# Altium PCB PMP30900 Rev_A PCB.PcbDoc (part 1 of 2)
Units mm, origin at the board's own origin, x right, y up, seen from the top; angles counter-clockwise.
Board outline 88.9 x 46.99 mm, 6 copper layers (Top Layer, Layer 2, Layer 3, Layer 4, Layer 5, Bottom Layer), stack 1.76 mm thick; 101 components, 54 nets, 324 pads, 212 vias.
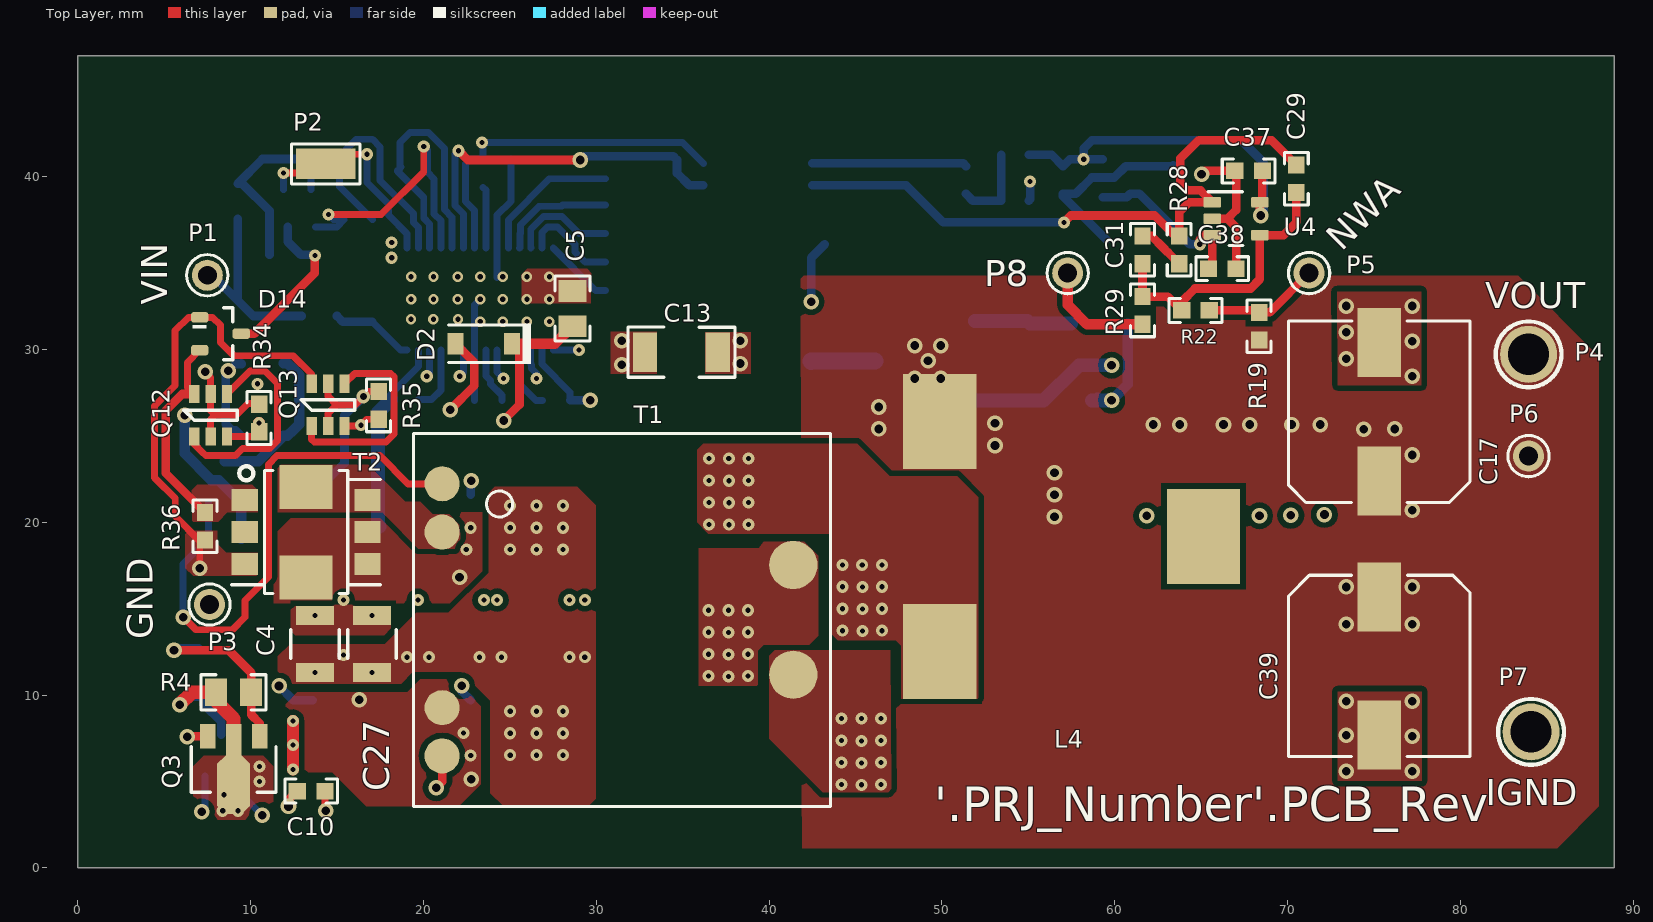
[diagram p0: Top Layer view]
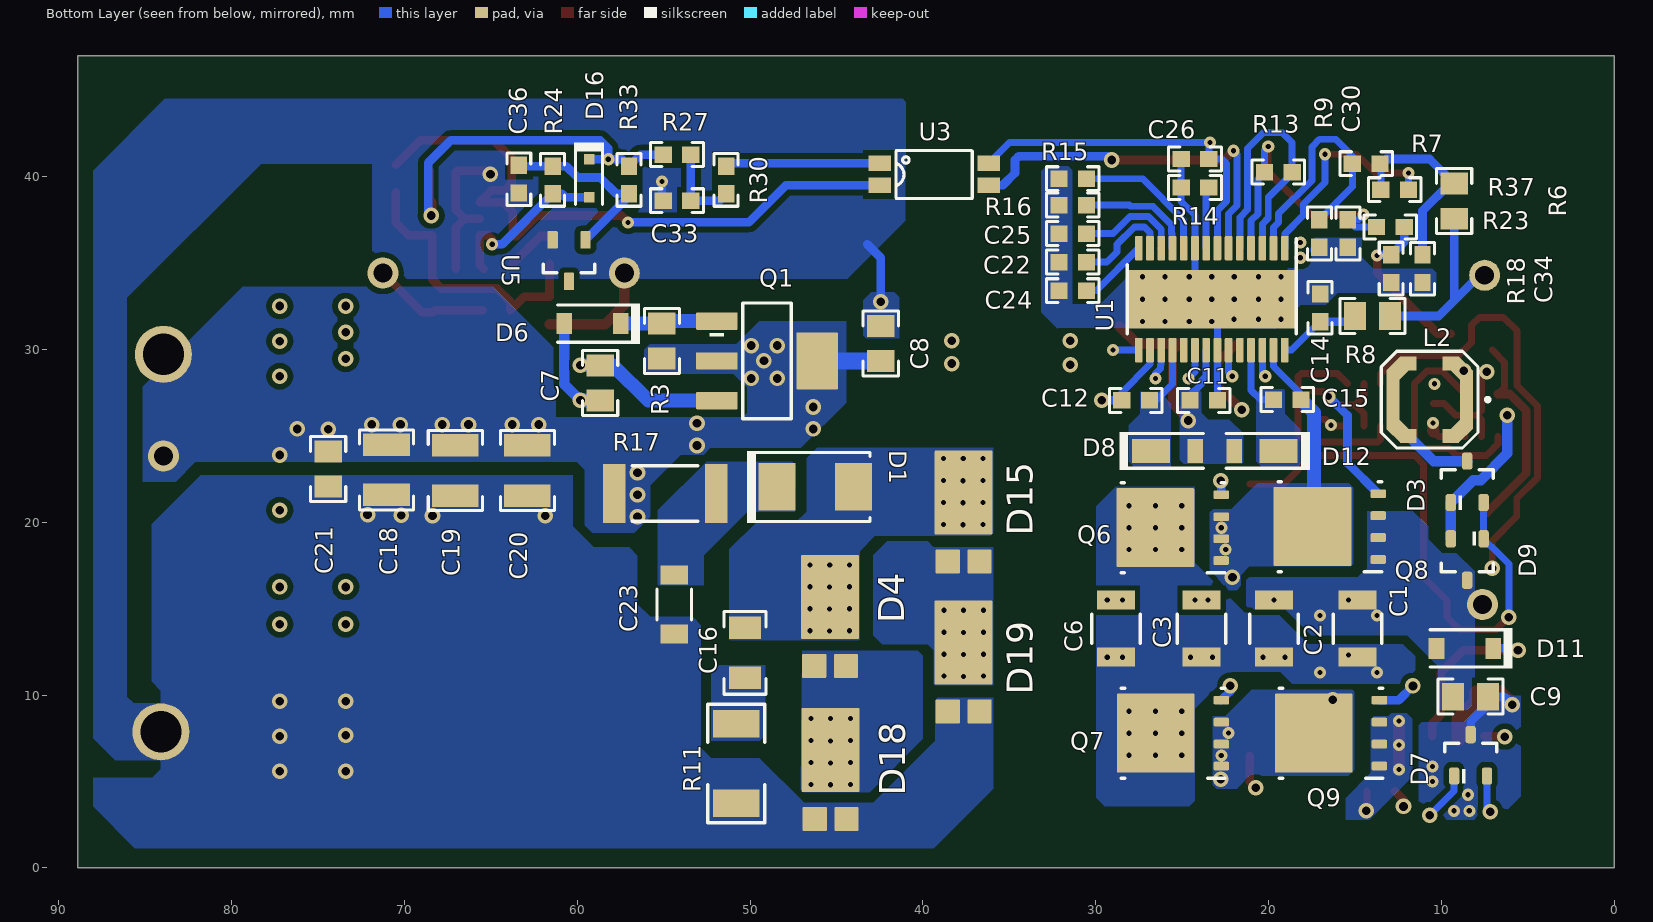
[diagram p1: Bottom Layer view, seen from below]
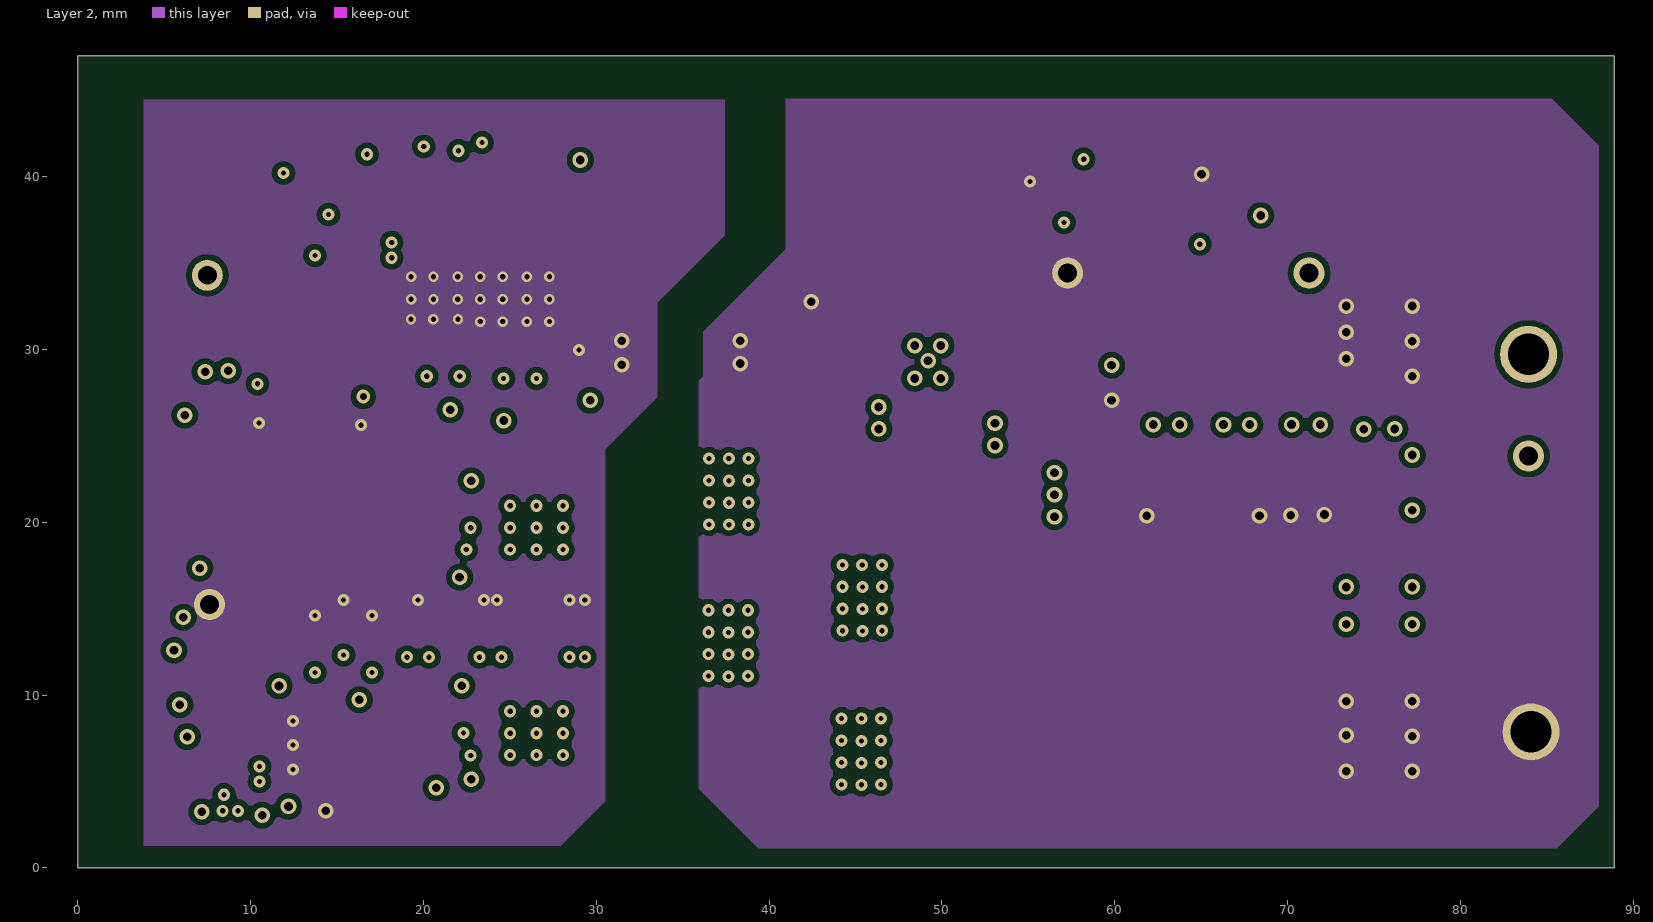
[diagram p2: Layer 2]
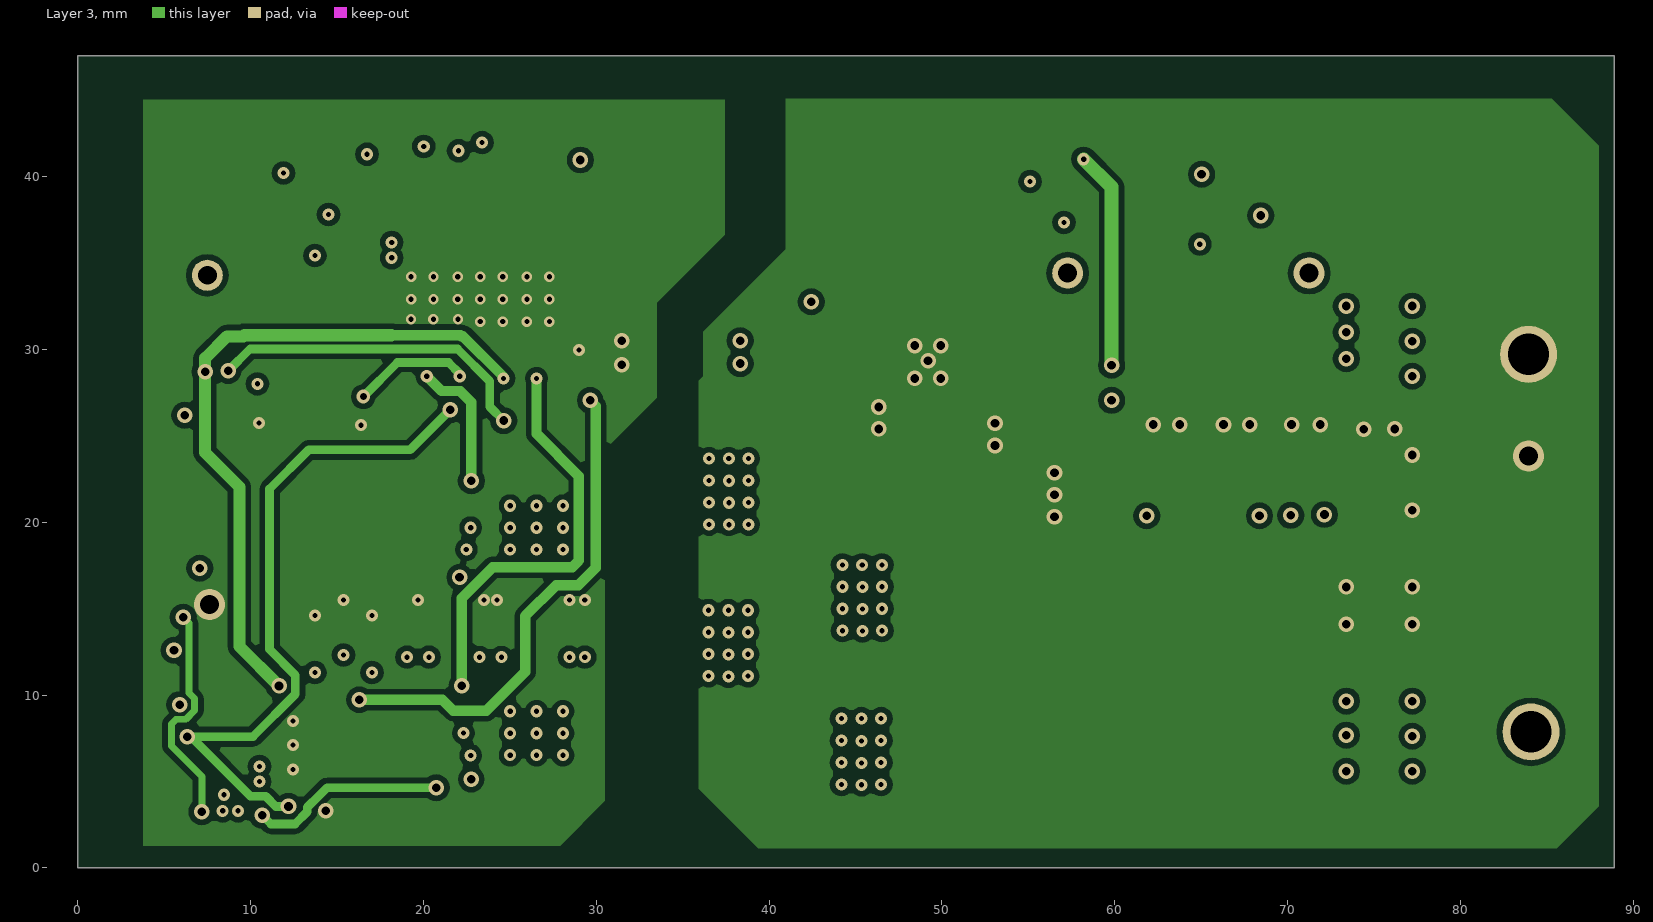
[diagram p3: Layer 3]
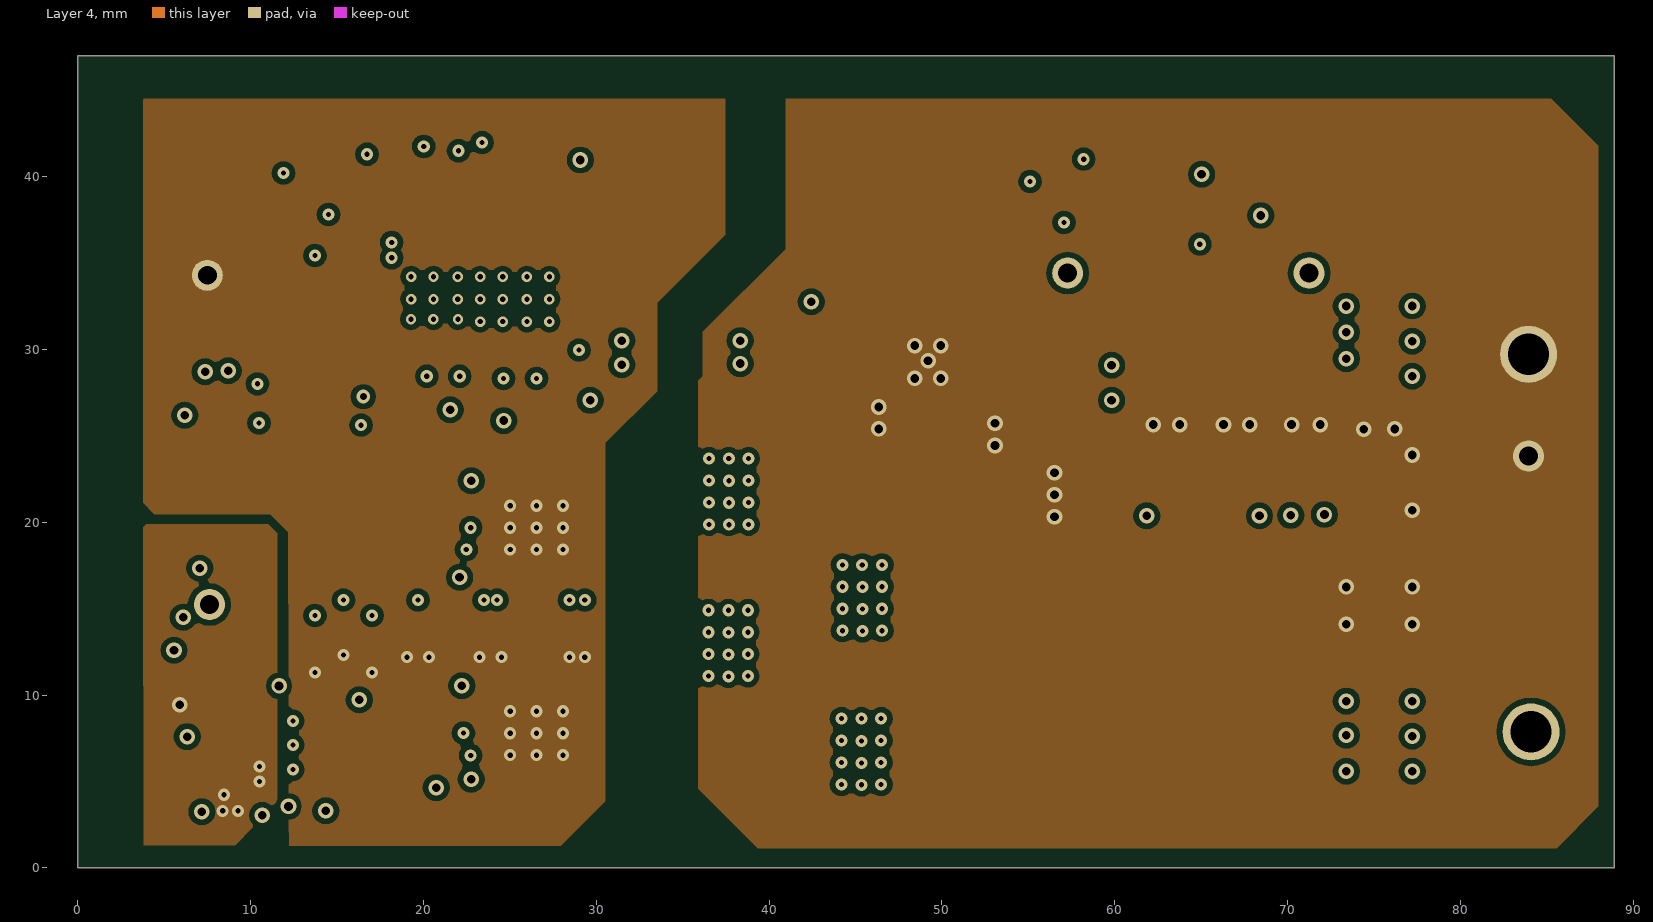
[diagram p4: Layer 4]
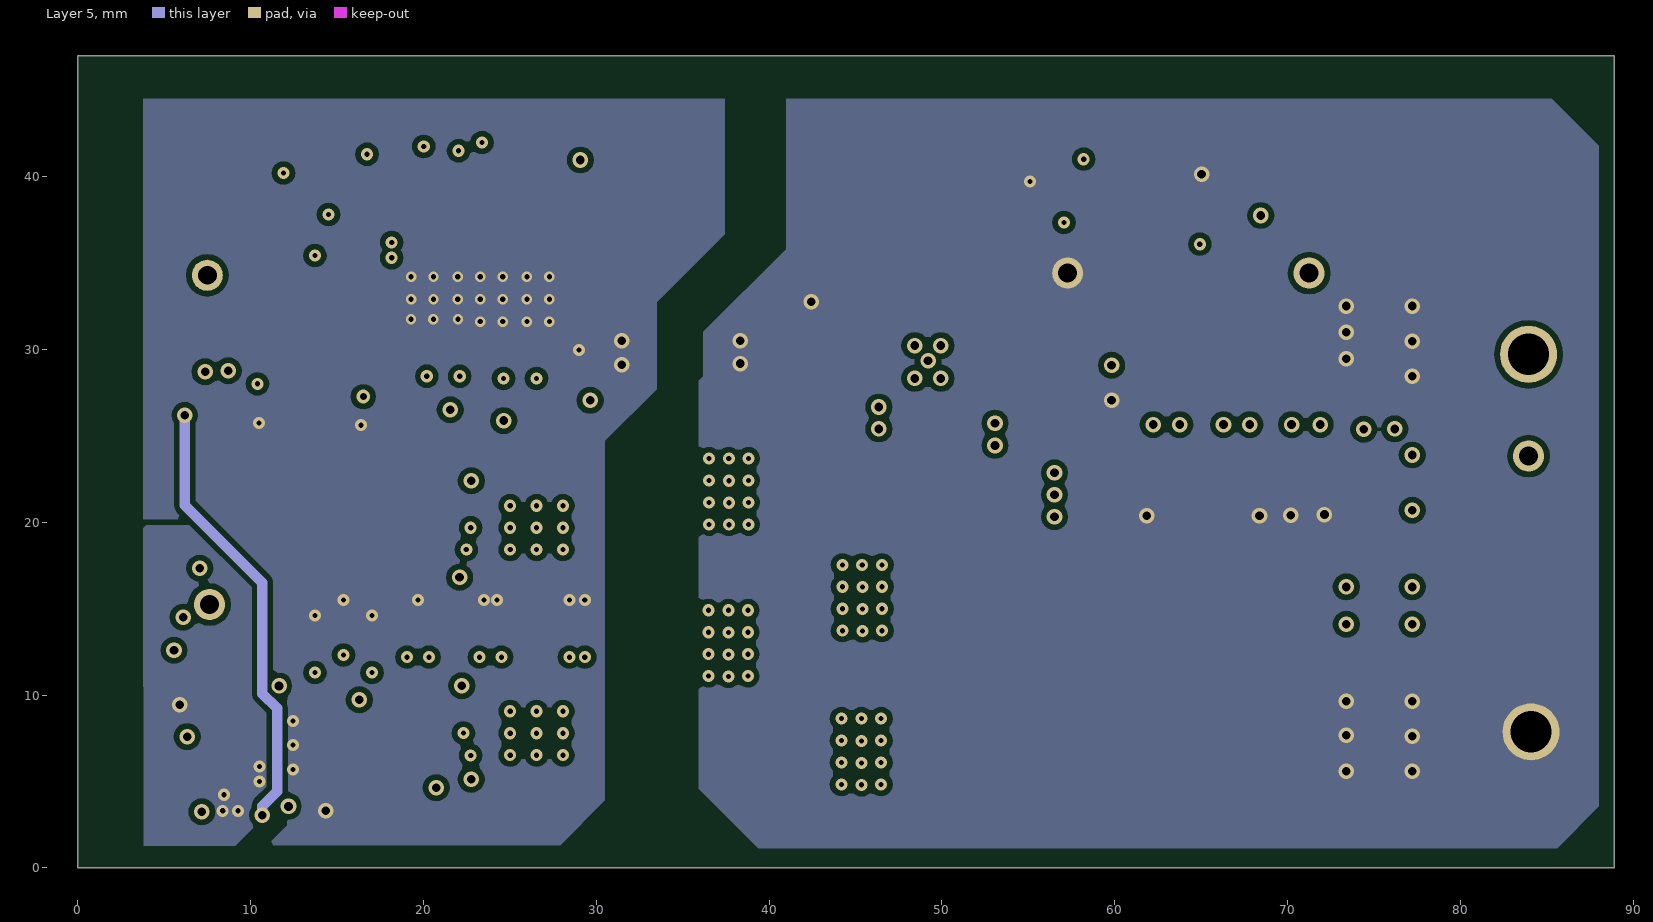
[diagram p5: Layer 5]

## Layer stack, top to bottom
Top Solder: solder mask 0.0102, Solder Resist, Dk 3.5
Top Layer: signal copper 0.07
Dielectric 1: prepreg 0.232, PP-006, Dk 4.1
Layer 2: signal copper 0.035
Dielectric 2: prepreg 0.36, PP-006, Dk 4.1
Layer 3: signal copper 0.035
Dielectric 3: prepreg 0.296, FR-4, Dk 4.8
Layer 4: signal copper 0.035
Dielectric 4: prepreg 0.36, PP-006, Dk 4.1
Layer 5: signal copper 0.035
Dielectric 5: prepreg 0.232, PP-006, Dk 4.1
Bottom Layer: signal copper 0.07
Bottom Solder: solder mask 0.0102, Solder Resist, Dk 3.5

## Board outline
0,0 88.9,0 88.9,46.99 0,46.99

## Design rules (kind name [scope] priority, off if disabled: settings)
AcuteAngle [All] p1: minimum=4.50000000000000E+0001 checktracksonly=FALSE
AssemblyTestPointUsage [All] p1: valid=2
BoardOutlineClearance BoardOutlineClearance_MountingHoles [OnCopper and InComponentClass('Mounting Holes')] p1: gap=1 ignorepadtopadclearanceinfootprint=FALSE
BoardOutlineClearance BoardOutlineClearance_Poly [OnCopper and IsPoly] p2: gap=0.4 ignorepadtopadclearanceinfootprint=FALSE
BoardOutlineClearance [OnCopper and Not InComponentClass('Logo') and not InComponentClass('FiducialMark') and not InRegion(1000,500,4000,800) and not InPoly] p3: gap=1.905 ignorepadtopadclearanceinfootprint=FALSE
Clearance Clearance_Keepouts [((IsTrack Or IsArc) And Not InPoly) And IsFree and IsKeepOut vs ((IsTrack Or IsArc) And Not InPoly) And IsFree and IsKeepOut] p1: gap=0 ignorepadtopadclearanceinfootprint=FALSE
Clearance Clearance_Poly [InPolygon] p2: gap=0.32 ignorepadtopadclearanceinfootprint=TRUE
Clearance Clearance_FiducialMark [IsKeepOut and InComponentClass('FiducialMark') vs IsPad and InComponentClass('FiducialMark')] p3: gap=0 ignorepadtopadclearanceinfootprint=FALSE
Clearance [All] p4: gap=0.2 ignorepadtopadclearanceinfootprint=TRUE
ComponentClearance ComponentClearance_MountingHoles_FiducialMarks [InComponentClass('Mounting Holes') vs InComponentClass('FiducialMark')] p1: gap=1.27 collisioncheckmode=3 verticalgap=0.254 showdistances=FALSE
ComponentClearance ComponentClearance_Shunt [InComponentClass('Header') vs InComponentClass('Shunt')] p2: gap=0 collisioncheckmode=3 verticalgap=0 showdistances=FALSE
ComponentClearance ComponentClearance_Logo [InComponentClass('Logo')] p3: gap=1.27 collisioncheckmode=3 verticalgap=0.254 showdistances=FALSE
ComponentClearance ComponentClearance_ScrewToNut [(HasFootprint('NY PMS 440 0025 PH')) vs (HasFootprint('Keystone_1902C'))] p4: gap=0.127 collisioncheckmode=3 verticalgap=0.254 showdistances=FALSE
ComponentClearance ComponentClearance_MountingHoles [InComponentClass('Mounting Holes')] p5: gap=6.35 collisioncheckmode=3 verticalgap=2540 showdistances=FALSE
ComponentClearance ComponentClearance_SmallPassives [HasFootprint('0201*') or HasFootprint('0402*') or HasFootprint('0508') or HasFootprint('0603*') or HasFootprint('0612') or HasFootprint('0805*') or HasFootprint('0815*') or HasFootprint('0830*') or HasFootprint('1206*') or HasFootprint('1210*') or HasFootprint('1808*') or HasFootprint('1812*') or HasFootprint('1825*') or HasFootprint('2010*') or HasFootprint('2220*') or HasFootprint('2225*') or HasFootprint('2512*') or HasFootprint('2728*') or HasFootprint('3518*') vs HasFootprint('0201*') or HasFootprint('0402*') or HasFootprint('0508') or HasFootprint('0603*') or HasFootprint('0612') or HasFootprint('0805*') or HasFootprint('0815*') or HasFootprint('0830*') or HasFootprint('1206*') or HasFootprint('1210*') or HasFootprint('1808*') or HasFootprint('1812*') or HasFootprint('1825*') or HasFootprint('2010*') or HasFootprint('2220*') or HasFootprint('2225*') or HasFootprint('2512*') or HasFootprint('2728*') or HasFootprint('3518*')] p6: gap=0.38 collisioncheckmode=3 verticalgap=0.254 showdistances=FALSE
ComponentClearance ComponentClearance_THtoSMT [IsThruComponent vs IsSMTComponent] p7: gap=1.016 collisioncheckmode=3 verticalgap=0.762 showdistances=FALSE
ComponentClearance ComponentClearance_THtoTH [IsThruComponent vs IsThruComponent] p8: gap=0.762 collisioncheckmode=3 verticalgap=0.762 showdistances=FALSE
ComponentClearance [All] p9: gap=0.762 collisioncheckmode=3 verticalgap=0.254 showdistances=FALSE
DiffPairsRouting [All] p1: maxlimit=2.54 minlimit=0.254 mostfreqgap=0.254 toplayer_minwidth=0.381 toplayer_maxwidth=0.381 toplayer_prefwidth=0.381 midlayer1_minwidth=0.381 midlayer1_maxwidth=0.381 midlayer1_prefwidth=0.381 midlayer2_minwidth=0.381 midlayer2_maxwidth=0.381 midlayer2_prefwidth=0.381 midlayer3_minwidth=0.381 midlayer3_maxwidth=0.381 midlayer3_prefwidth=0.381 midlayer4_minwidth=0.381 midlayer4_maxwidth=0.381 midlayer4_prefwidth=0.381 bottomlayer_minwidth=0.381 bottomlayer_maxwidth=0.381 bottomlayer_prefwidth=0.381 maxuncoupledlength=25.4
FabricationTestPointUsage TestPointUsage [All] p1: valid=2 allowmultiple=FALSE
FabricationTestpoint Testpoint [All] p1: side=3 testpointundercomponent=TRUE minsize=1.016 maxsize=2.54 preferedsize=1.524 minholesize=0 maxholesize=1.016 preferedholesize=0.813 testpointgrid=0.025 allowsidetop=TRUE allowsidebottom=TRUE usegrid=TRUE gridtolerance=0
FanoutControl Fanout_LCC [IsLCC] p1: bgadir=Out bgaviamode=Centered fanoutstyle=Auto fanoutdirection=Alternating viagrid=0.025 // Fanout_LCC (Default Rule)
FanoutControl Fanout_BGA [IsBGA] p2: bgadir=Out bgaviamode=Centered fanoutstyle=Auto fanoutdirection=Alternating viagrid=0.025 // Fanout_BGA (Default Rule)
FanoutControl Fanout_Default [All] p4: bgadir=Out bgaviamode=Centered fanoutstyle=Auto fanoutdirection=Alternating viagrid=0.025 // Fanout_Default (Default Rule)
FanoutControl Fanout_Small [(CompPinCount < 5)] p5: bgadir=Out bgaviamode=Centered fanoutstyle=Auto fanoutdirection=OutThenIn viagrid=0.025 // Fanout_Small (Default Rule)
HoleSize [All] p1: absolutevalues=TRUE maxlimit=6.375 minlimit=0.3 maxpercent=80.000 minpercent=20.000
MinimumAnnularRing MinimumAnnularRing_ThermalPadVias [IsVia and InAnyComponent] p1: minimumring=0.15
MinimumAnnularRing [All] p2: minimumring=0.2
MinimumSolderMaskSliver MinimumSolderMaskSliver_Logo [InComponentClass('Logo') vs InComponentClass('Logo')] p1: minsoldermaskwidth=0.018
MinimumSolderMaskSliver [All] p2: minsoldermaskwidth=0.1
PlaneConnect [All] p1: planeconnectstyle=Relief reliefexpansion=0.254 reliefentries=4 reliefconductorwidth=0.254 reliefairgap=0.254
PolygonConnect PolygonConnect_1 [All vs InComponent('P5')] p1: connectstyle=NoConnect reliefconductorwidth=0.254 reliefentries=4 polygonreliefangle="90 Angle" airgapwidth=0.254
PolygonConnect [All] p2: connectstyle=Direct reliefconductorwidth=0.254 reliefentries=4 polygonreliefangle="90 Angle" airgapwidth=0.254
RoutingVias ThermalPadVias [IsVia and InAnyComponent] p1: holewidth=0.2 width=0.5 viastyle="Through Hole" minholewidth=0.2 minwidth=0.5 maxholewidth=0.33 maxwidth=0.6
RoutingVias [All] p2: holewidth=0.5 width=0.9 viastyle="Through Hole" minholewidth=0.3 minwidth=0.6 maxholewidth=1.016 maxwidth=1.651
SilkToBoardRegionClearance [Not ((IsComment or IsDesignator) And (Hide <> 'False')) and not InRegion(1000,500,4000,800)] p1:
SilkToSilkClearance SilkToSilkClearance_Pb-FreeLogo [(HasFootprint('Pb-Free_Overlay_Medium') OR HasFootprint('Pb-Free_Overlay_Small')) vs (HasFootprint('Pb-Free_Overlay_Medium') OR HasFootprint('Pb-Free_Overlay_Small'))] p1: silktosilkclearance=0
SilkToSilkClearance [All] p2: silktosilkclearance=0.1
SilkToSolderMaskClearance SilkToComponentPadClearance [(IsPad or IsFill or IsRegion) and InAnycomponent] p1: minsilkscreentomaskgap=0.127 clearancetoexposedcopper=TRUE
SilkToSolderMaskClearance "Silk to Solder Mask Opening" [All] p2: minsilkscreentomaskgap=0.1 clearancetoexposedcopper=FALSE
SolderMaskExpansion [All] p1: expansion=0.05 istentingtop=FALSE
UnRoutedNet [All] p1: checkbadconnections=TRUE
Width [All] p1: maxlimit=2.54 minlimit=0.152 preferedwidth=0.254 checkconnectedcopper=TRUE
14 further rules are at their usual default settings.

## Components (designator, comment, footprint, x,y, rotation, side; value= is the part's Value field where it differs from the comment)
C1 "C3225X5R1H106K250AB" 1210_280 14.859,13.843 r90 bottom value=10uF
C2 "C3225X5R1H106K250AB" 1210_280 19.685,13.843 r90 bottom value=10uF
C3 "C3225X5R1H106K250AB" 1210_280 23.876,13.843 r90 bottom value=10uF
C4 "C3225X5R1H106K250AB" 1210_280 13.716,12.954 r90 top value=10uF
C5 "GRM21BR71C225KA12L" 0805_HV 28.626,32.359 r90 top value=2.2uF
C6 "C3225X5R1H106K250AB" 1210_280 28.829,13.843 r90 bottom value=10uF
C7 "GRM21BR71E225KA73L" 0805_HV 58.674,28.067 r270 bottom value=2.2uF
C8 "GRM21AR72A224KAC5L" 0805_HV 42.439,30.337 r90 bottom value=0.22uF
C9 "GRM21BR71H105KA12L" 0805_HV 8.307,9.91 r0 bottom value=1uF
C10 "C1608X7R1C105K080AC" 0603 13.5,4.445 r0 top value=1uF
C11 "C1608X7R1C105K080AC" 0603 23.749,27.051 r180 bottom value=1uF
C12 "06033C104KAT2A" 0603 27.686,27.051 r180 bottom value=0.1uF
C13 "C1808C272KGRACTU" 1808 34.925,29.837 r0 top value=2700pF
C14 "GRM188R72A104KA35D" 0603 17.018,32.409 r90 bottom value=0.1uF
C15 "06033C104KAT2A" 0603 18.916,27.096 r0 bottom value=0.1uF
C16 "GRM31A5C2J101JW01D" 1206 50.292,12.446 r270 bottom value=100pF
C17 "EEHZC1K470P" SM_RADIAL_10BMM 75.311,26.393 r90 top value=47uF
C18 "GRM32ER72A225KA35L" 1210_270 71.037,23.03 r270 bottom value=2.2uF
C19 "GRM32ER72A225KA35L" 1210_270 67.056,22.995 r270 bottom value=2.2uF
C20 "GRM32ER72A225KA35L" 1210_270 62.885,22.995 r270 bottom value=2.2uF
C21 "C0805C104K1RACTU" 0805_HV 74.413,23.084 r270 bottom value=0.1uF
C22 "GRM188R71C223KA01D" 0603 31.331,35.052 r0 bottom value=0.022uF
C23 "GRM31CR72E104KW03L" 1206_180 54.379,15.239 r270 bottom value=0.1uF
C24 "GRM188R71C563KA01D" 0603 31.331,33.401 r0 bottom value=0.056uF
C25 "GRM188R71C103KA01D" 0603 31.331,36.703 r0 bottom value=0.01uF
C26 "06033C104KAT2A" 0603 24.257,41.021 r0 bottom value=0.1uF
C27 "C3225X5R1H106K250AB" 1210_280 17.018,12.954 r90 top value=10uF
C29 "GRM1885C1H470JA01D" 0603 70.506,39.878 r90 top value=47pF
C30 "C1608C0G1H101J080AE" 0603 15.409,36.707 r270 bottom value=100pF
C31 "GRM188R71C103KA01D" 0603 63.73,35.765 r90 top value=0.01uF
C33 "GRM188R71C103KA01D" 0603 54.229,38.608 r0 bottom value=0.01uF
C34 "GRM1885C1E102JA01D" 0603 11.091,34.675 r270 bottom value=1000pF
C36 "GRM1885C1E102JA01D" 0603 63.385,39.855 r270 bottom value=1000pF
C37 "06033C104KAT2A" 0603 67.746,40.33 r0 top value=0.1uF
C38 "GRM188R70J474KA01D" 0603 66.222,34.671 r0 top value=0.47uF
C39 "EEHZC1K470P" SM_RADIAL_10BMM 75.311,11.684 r270 top value=47uF
D1 "MBRS3200T3G" SMB 46.228,22.048 r180 bottom value=200V
D2 "B130LAW-7-F" SOD-123 23.487,30.327 r180 top value=30V
D3 "CMPSH-3CE" SOT-23 8.506,22.34 r90 bottom value=40V
D4 "MBR10200UPS" TO-277 45.37,13.679 r0 bottom
D6 "MMSZ5243B-7-F" SOD-123 59.118,31.496 r0 bottom value=13V
D7 "CMPSH-3CE" SOT-23 8.307,6.512 r90 bottom value=40V
D8 "DFLS1100-7" PowerDI123 25.527,24.13 r180 bottom value=100V
D9 "CMPSH-3AE" SOT-23 8.506,17.843 r270 bottom value=40V
D11 "MMSZ5241B-7-F" SOD-123 8.636,12.7 r0 bottom value=11V
D12 "DFLS1100-7" PowerDI123 20.701,24.13 r0 bottom value=100V
D14 "CMPSH-3CE" SOT-23 8.254,30.909 r0 top value=40V
D15 "MBR10200UPS" TO-277 37.643,19.722 r0 bottom
D16 "BAT54WS-7-F" SOD-323 59.315,39.907 r270 bottom value=30V
D18 "MBR10200UPS" TO-277 45.339,4.826 r0 bottom
D19 "MBR10200UPS" TO-277 37.643,11.049 r0 bottom
L2 "LPS5030-225MLB" LPS5030 10.68,27.096 r0 bottom value=2.2mH
L4 "SER2013-472MLB" LIBRARYSOURCE=Vault 57.511,19.182 r0 top
P1 "3104-2-00-34-00-00-08-0" 3104-2 7.493,34.29 r0 top
P2 "5015" Testpoint_Keystone_Miniature 14.351,40.746 r0 top
P3 "3104-2-00-34-00-00-08-0" 3104-2 7.62,15.24 r0 top
P4 "3231-2-00-34-00-00-08-0" 3231-2 83.947,29.718 r0 top
P5 "3104-2-00-34-00-00-08-0" 3104-2 71.247,34.417 r0 top
P6 "3104-2-00-34-00-00-08-0" 3104-2 83.947,23.827 r0 top
P7 "3231-2-00-34-00-00-08-0" 3231-2 84.09,7.874 r0 top
P8 "3104-2-00-34-00-00-08-0" 3104-2 57.277,34.417 r0 top
Q1 "FZT493TA" SOT-223 49.022,29.337 r180 bottom
Q3 "FCX690BTA" SOT-89-3 9.017,5.715 r270 top value="45 V"
Q6 "CSD18504Q5A" DQJ0008A 25.538,19.685 r0 bottom value=40V
Q7 "CSD18504Q5A" DQJ0008A 25.526,7.8 r0 bottom value=40V
Q8 "CSD18504Q5A" DQJ0008A 16.452,19.748 r0 bottom value=40V
Q9 "CSD18504Q5A" DQJ0008A 16.382,7.8 r0 bottom value=40V
Q12 "DMN5L06DMK-7" SOT-26 7.681,26.194 r90 top value=50V
Q13 "DMN5L06DMK-7" SOT-26 14.482,26.793 r90 top value=50V
R3 "ERJ-6GEYJ104V" 0805_HV 55.104,30.48 r270 bottom value=100k
R4 "ERJ-6GEYJ512V" 0805_HV 9.017,10.16 r180 top value=5.1k
R6 "CRCW0805100KFKEA" 0805_HV 9.256,38.579 r270 bottom value=100k
R7 "CRCW06032K61FKEA" 0603 14.351,40.746 r180 bottom value=2.61k
R8 "ERJ-6GEYJ200V" 0805_HV 13.979,31.934 r180 bottom value=20
R9 "CRCW06031K58FKEA" 0603 17.06,36.707 r90 bottom value=1.58k
R11 "CRCW2010100RJNEF" 2010 50.797,6.044 r90 bottom value=100
R13 "CRCW06031K69FKEA" 0603 19.431,40.259 r180 bottom value=1.69k
R14 "CRCW060324K0JNEA" 0603 24.257,39.37 r180 bottom value=24k
R15 "CRCW060330K1FKEA" 0603 31.331,39.878 r180 bottom value=30.1k
R16 "CRCW060320K0FKEA" 0603 31.331,38.354 r180 bottom value=20.0k
R17 "CRCW251210K0JNEG" 2512 54.921,21.66 r0 bottom value=10k
R18 "CRCW060315R0FKEA" 0603 12.902,34.678 r90 bottom value=15.0
R19 "ERJ-3EKF49R9V" 0603 68.351,31.344 r270 top value=49.9
R22 "RC0603FR-07680KL" 0603 64.672,32.258 r0 top value=680k
R23 "CRCW0603499RFKEA" 0603 12.954,37.084 r180 bottom value=499
R24 "CRCW06035K11FKEA" 0603 61.427,39.807 r90 bottom value=5.11k
R27 "CRCW060347R0JNEAHP" 0603 54.229,41.275 r0 bottom value=47
R28 "CRCW060310K0FKEA" 0603 61.606,35.765 r270 top value=10.0k
R29 "CRCW060315K0FKEA" 0603 61.606,32.258 r270 top value=15.0k
R30 "CRCW06031K82FKEA" 0603 51.39,39.807 r270 bottom value=1.82k
R33 "RC0603FR-07100KL" 0603 57.006,39.807 r90 bottom value=100k
R34 "CRCW060310K0FKEA" 0603 10.49,26.035 r90 top value=10.0k
R35 "CRCW060310K0FKEA" 0603 17.409,26.761 r90 top value=10.0k
R36 "CRCW060310K0FKEA" 0603 7.357,19.768 r90 top value=10.0k
R37 "CRCW06030000Z0EA" 0603 12.7,39.243 r0 bottom value=0
T1 "ZB1292-AL" PA0876 31.496,14.351 r0 top
T2 "PA1005.100NL" P82xx 13.208,19.431 r0 top
U1 "LM5045MHX/NOPB" PWP0028A_N 23.284,32.909 r270 bottom
U3 "TCMT1107" SOP-4 39.345,40.132 r180 bottom
U4 "LM8261M5X/NOPB" DBV0005A_N 67.023,37.565 r0 top
U5 "LM4041B12IDBZT" DBZ0003A_N 60.477,35.141 r270 bottom

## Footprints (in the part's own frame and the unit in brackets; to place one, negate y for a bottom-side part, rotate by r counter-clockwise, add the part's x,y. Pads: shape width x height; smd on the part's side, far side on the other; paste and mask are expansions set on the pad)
0603 [mm] "0603 from SM-752 data"
  rect 1x0.95 smd: 1(-0.8,0) 2(0.8,0)
  silkscreen extent -1.52,-0.69 1.52,0.69, body extent -0.87,-0.47 0.87,0.47, height 1
0805_HV [mil] "0805 with 30mil clearance between pads"
  rect 50x63 smd: 1(-40,0) 2(40,0)
  silkscreen extent -74,-40 74,40, body extent -43,-29 43,29, height 57
1206 [mm] "1206 from SM-752 data"
  rect 1.3x1.85 smd: 1(-1.45,0) 2(1.45,0)
  silkscreen extent -2.4,-1.21 2.4,1.21, body extent -1.7,-0.9 1.7,0.9, height 1.35
1206_180 [mm] "1206_180"
  rect 1.1x1.6 smd: 1(-1.7,0) 2(1.7,0)
  silkscreen extent -0.9,-1 0.9,1, body extent -1.75,-0.95 1.75,0.95, height 1.8
1210_270 [mm] "1210"
  rect 1.3x2.7 smd: 1(-1.45,0) 2(1.45,0)
  silkscreen extent -2.32,-1.57 2.32,1.57, body extent -1.7,-1.35 1.7,1.35, height 2.7
1210_280 [mm] "SMD, 2-Leads, Body 3.6x2.8mm, Height 2.8mm"
  rect 1.1x2.2 smd: 1(-1.65,0) 2(1.65,0)
  silkscreen extent -0.84,-1.4 0.84,1.4, body extent -1.8,-1.4 1.8,1.4, height 2.8
1808 [mm] "Chip Capacitor, Body 4.6x2.0mm, IPC Medium Density"
  rect 1.4x2.3 smd: 1(-2.1,0) 2(2.1,0)
  silkscreen extent -3.1,-1.45 3.1,1.45, body extent -2.47,-1.2 2.47,1.2, height 2.03
2010 [mm] "Chip Capacitor, Body 5.08x2.54mm, IPC Medium Density"
  rect 1.6x2.7 smd: 1(-2.3,0) 2(2.3,0)
  silkscreen extent -3.42,-1.65 3.42,1.65, body extent -2.73,-1.45 2.73,1.45, height 1.66
2512 [mm] "Chip Resistor, Body 6.3x3.2mm, IPC Medium Density"
  rect 1.3x3.4 smd: 1(-2.95,0) 2(2.95,0)
  silkscreen extent -1.9,-1.6 1.9,1.6, body extent -3.22,-1.67 3.22,1.67, height 0.71
3104-2 [mm] "Mill-Max Printed Circuit Pins"
  round 1.8 hole 1.092: 1(0,0)
  silkscreen extent -1.19,-1.19 1.19,1.19, body extent -0.88,-0.89 0.9,0.89, height 1.68
3231-2 [mil] "Mill-Max Printed Circuit Pin"
  round 130 hole 94: 1(0,0)
  silkscreen extent -75,-75 75,75, body extent -62,-63 63,62, height 78
DBV0005A_N [mm] "SOT23, 5-Leads, Body 2.9x1.6mm, Pitch 0.95mm, Lead Span 2.8mm, IPC Medium Density"
  rrect17% 1x0.6 smd: 1(-1.375,0.95) 2(-1.375,0) 3(-1.375,-0.95) 4(1.375,-0.95) 5(1.375,0.95)
  silkscreen extent -1.63,-1.55 0.38,1.55, body extent -1.42,-1.46 1.42,1.46, height 1.09
DBZ0003A_N [mm] "SOT23, 3-Leads, Body 2.9x1.3mm, Pitch 0.95mm, Lead Span 2.4mm, IPC Medium Density"
  rrect17% 1x0.6 smd: 1(-1.2,0.95) 2(-1.2,-0.95) 3(1.2,0)
  silkscreen extent 0.2,-1.5 0.7,1.5, body extent -1.26,-1.46 1.26,1.46, height 0.98
DQJ0008A [mm] "SMD, 8-Leads, Body 5.75x4.9mm"
  rrect39% 0.91x0.51 smd paste-0.05 mask-0.05: 1(-2.795,1.905) 2(-2.795,0.635) 3(-2.795,-0.635) 4(-2.795,-1.905) 5(2.795,-1.905) 6(2.795,-0.635) 7(2.795,0.635) 8(2.795,1.905)
  rrect8% 1.58x1.25 on Bottom Paste: 9(-0.38,-1.45) 9(-0.38,0) 9(-0.38,1.45) 9(1.4,-1.45) 9(1.4,0) 9(1.4,1.45)
  rrect3% 3.48x4.47 on Bottom Solder: 9(0.55,0)
  rrect2% 4.49x4.57 smd paste-2.5 mask-2.5: 9(1.005,0)
  silkscreen extent -3,-2.6 3,2.6, body extent -3.13,-2.45 3.13,2.45, height 1.15
LIBRARYSOURCE=Vault [mm]
  rect 4.25x5.5 smd: 1(-7.625,6.65) 2(-7.625,-6.65) 3(7.625,0)
  body extent -9.6,-11.18 9.6,11.32, height 10.4
LPS5030 [mm] "Coilcraft recommended land pattern.  Document 581-2, rev 10/06/08"
  rect 0.75x3.4 smd: 1(-2.125,0) 2(2.125,0)
  rect 1.131x0.92 smd rot 135: 1(-1.776,-1.776) 2(1.776,1.776)
  rect 1.131x0.92 smd rot 45: 1(-1.776,1.776) 2(1.776,-1.776)
  rect 0.95x0.8 smd: 1(-1.225,-2.1) 1(-1.225,2.1) 2(1.225,-2.1) 2(1.225,2.1)
  silkscreen extent -3.45,-2.8 2.8,2.8, body extent -2.5,-2.5 2.5,2.5, height 3.02
P82xx [mil] "Pulse recommended land pattern"
  rect 60x50 smd: 1(-140,73) 2(-140,0) 3(-140,-73) 4(140,-73) 5(140,0) 6(140,73)
  rect 120x100 smd: 7(0,-103) 8(0,103)
  silkscreen extent -170,-140 170,150, body extent -95,-140 95,140, height 215
PA0876 [mil] "Recommended land pattern for Pulse PA0876NL transformer"
  round 80 smd: 1(-410,310) 2(-410,200) 5(-410,-200) 6(-410,-310)
  round 110 smd: 8(390,-125) 10(390,125)
  silkscreen extent -475,-425 475,425, body extent -460,-425 460,425, height 382
PowerDI123 [mm] "Diodes Inc recommended land pattern, document number DS30628 Rev. 6-2"
  rect 2.2x1.4 smd: 1(-1.275,0)
  rect 0.9x1.4 smd: 2(1.275,0)
  silkscreen extent -3.1,-1.09 1.76,1.09, body extent -2.37,-0.96 1.53,0.97, height 1
PWP0028A_N [mm] "TSOP, 28-Leads, Body 9.7x4.4mm, Pitch 0.65mm, Exposed Pad, IPC Medium Density"
  rrect22% 1.4x0.45 smd: 1(-2.95,4.225) 2(-2.95,3.575) 3(-2.95,2.925) 4(-2.95,2.275) 5(-2.95,1.625) 6(-2.95,0.975) 7(-2.95,0.325) 8(-2.95,-0.325) 9(-2.95,-0.975) 10(-2.95,-1.625) 11(-2.95,-2.275) 12(-2.95,-2.925) 13(-2.95,-3.575) 14(-2.95,-4.225) 15(2.95,-4.225) 16(2.95,-3.575) 17(2.95,-2.925) 18(2.95,-2.275) 19(2.95,-1.625) 20(2.95,-0.975) 21(2.95,-0.325) 22(2.95,0.325) 23(2.95,0.975) 24(2.95,1.625) 25(2.95,2.275) 26(2.95,2.925) 27(2.95,3.575) 28(2.95,4.225)
  rrect3% 3.4x9.7 smd paste-1.7 mask-1.7: 29(0,0)
  rrect3% 3x5.5 on Bottom Paste: 29(0,0)
  rrect3% 3x5.5 on Bottom Solder: 29(0,0)
  silkscreen extent -3.5,-4.9 2,4.9, body extent -3.21,-4.85 3.21,4.85, height 1
SM_RADIAL_10BMM [mm] "Nichicon 10x10"
  rect 4x2.5 smd: 1(-4,0) 2(4,0)
  silkscreen extent -5.25,-5.25 5.25,5.25, body extent -5.25,-5.25 5.25,5.25, height 10.5
SMB [mm] "Molded Diode, 2-Leads, Body 5.4x3.6mm, IPC Medium Density, based on OnSemi component dimensions"
  rect 2.159x2.743 smd: 1(-2.21,0) 2(2.21,0)
  silkscreen extent -3.94,-2.08 3.18,2.08, body extent -2.7,-1.8 2.7,1.8, height 2.32
SOD-123 [mm] "On Semi recommended land pattern"
  rect 0.915x1.22 smd: 1(-1.637,0) 2(1.637,0)
  silkscreen extent -2.74,-1.17 2.03,1.17, body extent -1.93,-0.9 1.93,0.9, height 1.35
SOD-323 [mm] "NXP recommended land pattern"
  rect 0.6x0.6 smd paste-0.05: 1(-1.1,0) 2(1.1,0)
  silkscreen extent -2.06,-0.86 1.53,0.86, body extent -1.3,-0.67 1.3,0.68, height 1.1
SOP-4 [mm] "Vishay Half Pitch Mini-Flat Package"
  rect 1.3x0.9 smd: 1(-3.15,0.635) 2(-3.15,-0.635) 3(3.15,-0.635) 4(3.15,0.635)
  silkscreen extent -2.2,-1.41 2.2,1.39, body extent -3.5,-1.4 3.5,1.4, height 2.12
SOT-23 [mm] "SOT23, 3-Leads, Body 2.9x1.3mm, Pitch 0.95mm, Lead Span 2.5mm, IPC Medium Density"
  rrect50% 1x0.6 smd: 1(-1.2,0.95) 2(-1.2,-0.95) 3(1.2,0)
  silkscreen extent -1.62,-1.5 0.7,1.5, body extent -1.16,-1.45 1.21,1.45, height 1
SOT-26 [mm] "SOT23, 6-Leads, Body 3.1x3.0mm (max), Pitch 0.95mm, IPC Medium Density based on Diodes Inc ap02002.pdf rev 29"
  rect 1.05x0.6 smd: 1(-1.225,0.95) 2(-1.225,0) 3(-1.225,-0.95) 4(1.225,-0.95) 5(1.225,0) 6(1.225,0.95)
  silkscreen extent -0.3,-1.55 0.3,1.55, body extent -1.5,-1.5 1.5,1.5, height 1.3
SOT-89-3 [mm] "SOT, 3-Leads, Body 4.6 x 2.6 mm, Pitch 1.5mm"
  rect 1.4x0.9 smd: 1(-1.9,1.5) 3(-1.9,-1.5)
  rect 1.8x0.9 smd: 2(-1.7,0)
  oct 3.4x1.9 smd: 4(0.9,0)
  silkscreen extent -1.3,-2.45 1.33,2.45, body extent -2.42,-2.28 1.83,2.32, height 1.62
SOT-223 [mm] "SOT223/SC73, 4-Leads, Body 6.5x3.5mm, Pitch 2.3mm, Lead Span 7mm, IPC Medium Density"
  rrect10% 2.4x1 smd: 1(-2.9,2.3) 2(-2.9,0) 3(-2.9,-2.3)
  rrect4% 2.4x3.3 smd: 4(2.9,0)
  silkscreen extent -3.32,-3.35 1.4,3.35, body extent -3.5,-3.25 3.5,3.25, height 1.62
Testpoint_Keystone_Miniature [mil] "Miniature SMT test point"
  rect 135x70 smd: 1(0,0)
  silkscreen extent -78,-46 78,45, body extent -52,-20 52,20, height 61
TO-277 [mm] "Comchip"
  rrect9% 1.4x1.39 smd: 1(-0.92,1.995) 2(0.92,1.995)
  rrect4% 3.36x4.86 smd: 3(0,-1.995)
  body extent -2,-3.98 2,2.52, height 1.35

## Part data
C1 C2 C3 C4 C6 C27: library part CMP-0009103-2, "CAP, CERM, 10 uF, 50 V, +/- 10%, X5R, 1210", Cap_Case=1210, Manufacturer=TDK, Supplier Part Number 1=445-9074-6-ND, TempCo=X5R, Tolerance_%=10%, Value1=Unknown, Value2=50V, ValueDisplayed=10uF
C5: library part CMP-0008329-2, "CAP, CERM, 2.2 uF, 16 V, +/- 10%, X7R, 0805", Cap_Case=0805, Manufacturer=MuRata, Supplier Part Number 1=490-3906-1-ND, TempCo=X7R, Tolerance_%=10%, Value1="0.004 ohm", Value2=16V, ValueDisplayed=2.2uF
C7: library part CMP-0008342-2, "CAP, CERM, 2.2 uF, 25 V, +/- 10%, X7R, 0805", Cap_Case=0805, Manufacturer=MuRata, Supplier Part Number 1=490-3331-1-ND, TempCo=X7R, Tolerance_%=10%, Value1="0.005 ohm", Value2=25V, ValueDisplayed=2.2uF
C8: library part CMP-0008249-2, "CAP, CERM, 0.22 uF, 100 V, +/- 10%, X7R, 0805", Cap_Case=0805, Manufacturer=MuRata, Supplier Part Number 1=GRM21AR72A224KAC5-ND, TempCo=X7R, Tolerance_%=10%, Value1=Unknown, Value2=100V, ValueDisplayed=0.22uF
C9: library part CMP-0008350-2, "CAP, CERM, 1 uF, 50 V, +/- 10%, X7R, 0805", Cap_Case=0805, Manufacturer=MuRata, Supplier Part Number 1=490-4736-1-ND, TempCo=X7R, Tolerance_%=10%, Value1=Unknown, Value2=50V, ValueDisplayed=1uF
C10 C11: library part CMP-0007037-4, "CAP, CERM, 1 uF, 16 V, +/- 10%, X7R, 0603", Cap_Case=0603, Manufacturer=TDK, Supplier Part Number 1=445-1604-1-ND, TempCo=X7R, Tolerance_%=10%, Value1="0.0057 ohm", Value2=16V, ValueDisplayed=1uF
C12 C15 C26 C37: library part CMP-0006753-4, "CAP, CERM, 0.1 uF, 25 V, +/- 10%, X7R, 0603", Cap_Case=0603, Manufacturer=AVX, Supplier Part Number 1=478-3714-1-ND, TempCo=X7R, Tolerance_%=10%, Value1="0.05 ohm", Value2=25V, ValueDisplayed=0.1uF
C13: library part CMP-0009316-2, "CAP, CERM, 2700 pF, 2000 V, +/- 10%, X7R, 1808", Cap_Case=1808, Manufacturer=Kemet, Supplier Part Number 1=399-4830-1-ND, TempCo=X7R, Tolerance_%=10%, Value1=Unknown, Value2=2000V, ValueDisplayed=2700pF
C14: library part CMP-0007469-4, "CAP, CERM, 0.1 uF, 100 V, +/- 10%, X7R, 0603", Cap_Case=0603, Manufacturer=MuRata, Supplier Part Number 1=490-3285-1-ND, TempCo=X7R, Tolerance_%=10%, Value1=Unknown, Value2=100V, ValueDisplayed=0.1uF
C16: library part CMP-0008884-2, "CAP, CERM, 100 pF, 630 V, +/- 5%, C0G/NP0, 1206", Cap_Case=1206, Manufacturer=MuRata, Supplier Part Number 1=490-5273-1-ND, TempCo=C0G/NP0, Tolerance_%=5%, Value1=Unknown, Value2=630V, ValueDisplayed=100pF
C17 C39: library part CMP-0012606-3, "CAP, Polymer Hybrid, 47 uF, 80 V, +/- 20%, 36 mohm, 10x10 SMD", Manufacturer=Panasonic, Tolerance_%=20%, Value1="36 mohm", Value2=80V, ValueDisplayed=47uF
C18 C19 C20: library part CMP-0009232-2, "CAP, CERM, 2.2 uF, 100 V, +/- 10%, X7R, 1210", Cap_Case=1210, Manufacturer=MuRata, Supplier Part Number 1=490-3385-1-ND, TempCo=X7R, Tolerance_%=10%, Value1="0.007 ohm", Value2=100V, ValueDisplayed=2.2uF
C21: library part CMP-0007722-2, "CAP, CERM, 0.1 uF, 100 V, +/- 10%, X7R, 0805", Cap_Case=0805, Manufacturer=Kemet, Supplier Part Number 1=399-3486-1-ND, TempCo=X7R, Tolerance_%=10%, Value1="0.064 ohm", Value2=100V, ValueDisplayed=0.1uF
C22: library part CMP-0007388-4, "CAP, CERM, 0.022 uF, 16 V, +/- 10%, X7R, 0603", Cap_Case=0603, Manufacturer=MuRata, Supplier Part Number 1=490-1527-1-ND, TempCo=X7R, Tolerance_%=10%, Value1=Unknown, Value2=16V, ValueDisplayed=0.022uF
C23: library part CMP-0008973-2, "CAP, CERM, 0.1 uF, 250 V, +/- 10%, X7R, 1206", Cap_Case=1206, Manufacturer=MuRata, Supplier Part Number 1=490-3542-1-ND, TempCo=X7R, Tolerance_%=10%, Value1=Unknown, Value2=250V, ValueDisplayed=0.1uF
C24: library part CMP-0007399-4, "CAP, CERM, 0.056 uF, 16 V, +/- 10%, X7R, 0603", Cap_Case=0603, Manufacturer=MuRata, Supplier Part Number 1=490-1530-1-ND, TempCo=X7R, Tolerance_%=10%, Value1=Unknown, Value2=16V, ValueDisplayed=0.056uF
C25 C31 C33: library part CMP-0007377-4, "CAP, CERM, 0.01 uF, 16 V, +/- 10%, X7R, 0603", Cap_Case=0603, Manufacturer=MuRata, Supplier Part Number 1=490-1525-1-ND, TempCo=X7R, Tolerance_%=10%, Value1=Unknown, Value2=16V, ValueDisplayed=0.01uF
C29: library part CMP-0007220-4, "CAP, CERM, 47 pF, 50 V, +/- 5%, C0G/NP0, 0603", Cap_Case=0603, Manufacturer=MuRata, Supplier Part Number 1=490-1419-1-ND, TempCo=C0G/NP0, Tolerance_%=5%, Value1=Unknown, Value2=50V, ValueDisplayed=47pF
C30: library part CMP-0006989-4, "CAP, CERM, 100 pF, 50 V, +/- 5%, C0G/NP0, 0603", Cap_Case=0603, Manufacturer=TDK, Supplier Part Number 1=445-173611-1-ND, TempCo=C0G/NP0, Tolerance_%=5%, Value1=Unknown, Value2=50V, ValueDisplayed=100pF
C34 C36: library part CMP-0007159-4, "CAP, CERM, 1000 pF, 25 V, +/- 5%, C0G/NP0, 0603", Cap_Case=0603, Manufacturer=MuRata, Supplier Part Number 1=GRM1885C1E102JA01D-ND, TempCo=C0G/NP0, Tolerance_%=5%, Value1=Unknown, Value2=25V, ValueDisplayed=1000pF
C38: library part CMP-0007364-4, "CAP, CERM, 0.47 uF, 6.3 V, +/- 10%, X7R, 0603", Cap_Case=0603, Manufacturer=MuRata, Supplier Part Number 1=GRM188R70J474KA01D-ND, TempCo=X7R, Tolerance_%=10%, Value1=Unknown, Value2=6.3V, ValueDisplayed=0.47uF
D1: library part CMP-0028599-2, "Diode, Schottky, 200 V, 3 A, SMB", Manufacturer="ON Semiconductor", Value1=3A, Value2=0.84V
D2: library part CMP-0028382-2, "Diode, Schottky, 30 V, 1 A, SOD-123", Manufacturer="Diodes Inc.", Value1=1A, Value2=0.38V
D3 D7 D14: library part CMP-0028514-2, "Diode, Schottky, 40 V, 0.2 A, SOT-23", Manufacturer="Central Semiconductor", Value1=0.2A, Value2=0.65V
D4 D15 D18 D19: library part CMP-0750173-1, "Diode, Schottky, 200 V, 10 A, TO-277B", Manufacturer=MCC, Value1=10A, Value2=0.67V
D6: library part CMP-0005752-4, "Diode, Zener, 13 V, 500 mW, SOD-123", Manufacturer="Diodes Inc.", Power_W=500mW, Value1=0.5W
D8 D12: library part CMP-0028516-2, "Diode, Schottky, 100 V, 1 A, PowerDI123", Manufacturer="Diodes Inc.", Value1=1A, Value2=0.77V
D9: library part CMP-0028513-2, "Diode, Schottky, 40 V, 0.2 A, SOT-23", Manufacturer="Central Semiconductor", Value1=0.2A, Value2=0.65V
D11: library part CMP-0005750-4, "Diode, Zener, 11 V, 500 mW, SOD-123", Manufacturer="Diodes Inc.", Power_W=500mW, Value1=0.5W
D16: library part CMP-0028458-2, "Diode, Schottky, 30 V, 0.2 A, SOD-323", Manufacturer="Diodes Inc.", Value1=0.2A, Value2=0.7V
L2: library part CMP-0062000-2, "Inductor, Shielded Drum Core, Ferrite, 2.2 mH, 0.08 A, 11 ohm, SMD", Manufacturer=Coilcraft, Value1="11 ohm", Value2=0.08A, ValueDisplayed=2.2mH
L4: library part SER2211-473, "Inductor, Shielded E Core, Ferrite, 47 uH, 4.4 A, 0.0107 ohm, SMD", Manufacturer=Coilcraft, Value1="0.0107 ohm", Value2=4.4A, ValueDisplayed=47uH
P1 P3 P5 P6 P8: library part CMP-0055001-1, "PCB Pin, Swage Mount, TH", Manufacturer=Mill-Max, Supplier Part Number 1=3104-200340000080-ND
P2: library part CMP-0055152-1, "Test Point, Miniature, SMT", Manufacturer=Keystone, Supplier Part Number 1=36-5015TR-ND
P4 P7: library part CMP-0055003-1, "PCB Pin, Swage Mount, TH", Manufacturer=Mill-Max, Supplier Part Number 1=3231-200340000080-ND
Q1: library part CMP-0000447-1, "Transistor, NPN, 100 V, 1 A, SOT-223", Manufacturer="Diodes Incorporated", Supplier Part Number 1=FZT857CT-ND, Value1="1 A", Value2=100
Q3: library part CMP-0000384-2, "Transistor, NPN, 45 V, 1 A, SOT-89", Manufacturer="Diodes Inc.", Supplier Part Number 1=FCX690BCT-ND, Value1="1 A"
Q6 Q7 Q8 Q9: library part CMP-0000708-1, "MOSFET, N-CH, 40 V, 15 A, DQJ0008A (VSONP-8)", Alternate Manufacturer=None, Manufacturer="Texas Instruments", Supplier Part Number 1=296-30572-1-ND, Value1=0.009, Value2="7.7 nC"
Q12 Q13: library part CMP-DMN5L06DMK-7, "MOSFET, 2-CH, N-CH, 50 V, 0.305 A, AEC-Q101, SOT-26", Alternate Manufacturer=None, Manufacturer="Diodes Inc.", Supplier Part Number 1=DMN5L06DMKDICT-ND
R3: library part CMP-0020622-3, "RES, 100 k, 5%, 0.125 W, AEC-Q200 Grade 0, 0805", Manufacturer=Panasonic, Power_W=125mW, Supplier Part Number 1=P100KACT-ND, TempCo="200 ppm/C", Tolerance_%=5%, Value2=0.125W, Value_Code=100k
R4: library part CMP-0020740-3, "RES, 5.1 k, 5%, 0.125 W, AEC-Q200 Grade 0, 0805", Manufacturer=Panasonic, Power_W=125mW, Supplier Part Number 1=P5.1KACT-ND, TempCo="200 ppm/C", Tolerance_%=5%, Value2=0.125W, Value_Code=5k10, ValueDisplayed=5.1k
R6: library part CMP-0020834-3, "RES, 100 k, 1%, 0.125 W, AEC-Q200 Grade 0, 0805", Manufacturer=Vishay-Dale, Power_W=125mW, Supplier Part Number 1=541-100KCCT-ND, TempCo="100 ppm/C", Tolerance_%=1%, Value2=0.125W, Value_Code=100k
R7: library part CMP-0022279-4, "RES, 2.61 k, 1%, 0.1 W, AEC-Q200 Grade 0, 0603", Manufacturer=Vishay-Dale, Power_W=100mW, Supplier Part Number 1=541-2.61KHCT-ND, TempCo="100 ppm/C", Tolerance_%=1%, Value2=0.1W, Value_Code=2k61, ValueDisplayed=2.61k
R8: library part CMP-0020668-3, "RES, 20, 5%, 0.125 W, AEC-Q200 Grade 0, 0805", Manufacturer=Panasonic, Power_W=125mW, Supplier Part Number 1=P20ACT-ND, TempCo="200 ppm/C", Tolerance_%=5%, Value2=0.125W, Value_Code=20R0, ValueDisplayed=20
R9: library part CMP-0022128-4, "RES, 1.58 k, 1%, 0.1 W, AEC-Q200 Grade 0, 0603", Manufacturer=Vishay-Dale, Power_W=100mW, Supplier Part Number 1=541-1.58KHCT-ND, TempCo="100 ppm/C", Tolerance_%=1%, Value2=0.1W, Value_Code=1k58, ValueDisplayed=1.58k
R11: library part CMP-0016046-3, "RES, 100, 5%, 0.75 W, AEC-Q200 Grade 0, 2010", Manufacturer=Vishay-Dale, Power_W=750mW, Supplier Part Number 1=541-100WCT-ND, TempCo="200 ppm/C", Tolerance_%=5%, Value2=0.75W, Value_Code=100R, ValueDisplayed=100
R13: library part CMP-0022131-4, "RES, 1.69 k, 1%, 0.1 W, AEC-Q200 Grade 0, 0603", Manufacturer=Vishay-Dale, Power_W=100mW, Supplier Part Number 1=541-1.69KHCT-ND, TempCo="100 ppm/C", Tolerance_%=1%, Value2=0.1W, Value_Code=1k69, ValueDisplayed=1.69k
R14: library part CMP-0025762-4, "RES, 24 k, 5%, 0.1 W, AEC-Q200 Grade 0, 0603", Manufacturer=Vishay-Dale, Power_W=100mW, Supplier Part Number 1=541-24KGCT-ND, TempCo="200 ppm/C", Tolerance_%=5%, Value2=0.1W, Value_Code=24k0, ValueDisplayed=24k
R15: library part CMP-0022324-4, "RES, 30.1 k, 1%, 0.1 W, AEC-Q200 Grade 0, 0603", Manufacturer=Vishay-Dale, Power_W=100mW, Supplier Part Number 1=541-30.1KHCT-ND, TempCo="100 ppm/C", Tolerance_%=1%, Value2=0.1W, Value_Code=30k1, ValueDisplayed=30.1k
R16: library part CMP-0022204-4, "RES, 20.0 k, 1%, 0.1 W, AEC-Q200 Grade 0, 0603", Manufacturer=Vishay-Dale, Power_W=100mW, Supplier Part Number 1=541-20.0KHCT-ND, TempCo="100 ppm/C", Tolerance_%=1%, Value2=0.1W, Value_Code=20k0, ValueDisplayed=20.0k
R17: library part CMP-0015868-3, "RES, 10 k, 5%, 1 W, AEC-Q200 Grade 0, 2512", Manufacturer=Vishay-Dale, Power_W=1W, Supplier Part Number 1=541-10KXCT-ND, TempCo="200 ppm/C", Tolerance_%=5%, Value_Code=10k0, ValueDisplayed=10k
R18: library part CMP-0022069-4, "RES, 15.0, 1%, 0.1 W, AEC-Q200 Grade 0, 0603", Manufacturer=Vishay-Dale, Power_W=100mW, Supplier Part Number 1=541-15.0HCT-ND, TempCo="100 ppm/C", Tolerance_%=1%, Value2=0.1W, Value_Code=15R0, ValueDisplayed=15.0
R19: library part CMP-0022707-2, "RES, 49.9, 1%, 0.1 W, AEC-Q200 Grade 0, 0603", Manufacturer=Panasonic, Power_W=100mW, Supplier Part Number 1=P49.9HCT-ND, TempCo="100 ppm/C", Tolerance_%=1%, Value2=0.1W, Value_Code=49R9, ValueDisplayed=49.9
R22: library part CMP-0023234-4, "RES, 680 k, 1%, 0.1 W, 0603", Manufacturer=Yageo, Power_W=100mW, Supplier Part Number 1=311-680KHRCT-ND, TempCo="100 ppm/C", Tolerance_%=1%, Value2=0.1W, Value_Code=680k
R23: library part CMP-0022446-5, "RES, 499, 1%, 0.1 W, AEC-Q200 Grade 0, 0603", Manufacturer=Vishay-Dale, Power_W=100mW, Supplier Part Number 1=541-499HCT-ND, TempCo="100 ppm/C", Tolerance_%=1%, Value2=0.1W, Value_Code=499R, ValueDisplayed=499
R24: library part CMP-0022509-4, "RES, 5.11 k, 1%, 0.1 W, AEC-Q200 Grade 0, 0603", Manufacturer=Vishay-Dale, Power_W=100mW, Supplier Part Number 1=541-5.11KHCT-ND, TempCo="100 ppm/C", Tolerance_%=1%, Value2=0.1W, Value_Code=5k11, ValueDisplayed=5.11k
R27: library part CMP-0025815-4, "RES, 47, 5%, 0.25 W, AEC-Q200 Grade 0, 0603", Manufacturer=Vishay-Dale, PartNumber=CRCW060347R0JNEA, Power_W=100mW, Supplier Part Number 1=541-47SACT-ND, TempCo="200 ppm/C", Tolerance_%=5%, Value2=0.25W, Value_Code=47R0, ValueDisplayed=47
R28 R34 R35 R36: library part CMP-0021998-4, "RES, 10.0 k, 1%, 0.1 W, AEC-Q200 Grade 0, 0603", Manufacturer=Vishay-Dale, Power_W=100mW, Supplier Part Number 1=541-10.0KHCT-ND, TempCo="100 ppm/C", Tolerance_%=1%, Value2=0.1W, Value_Code=10k0, ValueDisplayed=10.0k
R29: library part CMP-0022066-4, "RES, 15.0 k, 1%, 0.1 W, AEC-Q200 Grade 0, 0603", Manufacturer=Vishay-Dale, Power_W=100mW, Supplier Part Number 1=541-15.0KHCT-ND, TempCo="100 ppm/C", Tolerance_%=1%, Value2=0.1W, Value_Code=15k0, ValueDisplayed=15.0k
R30: library part CMP-0022134-4, "RES, 1.82 k, 1%, 0.1 W, AEC-Q200 Grade 0, 0603", Manufacturer=Vishay-Dale, Power_W=100mW, Supplier Part Number 1=541-1.82KHCT-ND, TempCo="100 ppm/C", Tolerance_%=1%, Value2=0.1W, Value_Code=1k82, ValueDisplayed=1.82k
R33: library part CMP-0022735-5, "RES, 100 k, 1%, 0.1 W, 0603", Manufacturer=Yageo, Power_W=100mW, Supplier Part Number 1=311-100KHRCT-ND, TempCo="100 ppm/C", Tolerance_%=1%, Value2=0.1W, Value_Code=100k
R37: library part CMP-0025697-4, "RES, 0, 5%, 0.1 W, AEC-Q200 Grade 0, 0603", Manufacturer=Vishay-Dale, Power_W=100mW, Supplier Part Number 1=541-0.0GCT-ND, TempCo="200 ppm/C", Tolerance_%=5%, Value2=0.1W, Value_Code=0000, ValueDisplayed=0
T1: library part CMP-0030387-2, "High Frequency Planar Transformer", Manufacturer=Coilcraft
T2: library part CMP-0030386-2, "SMT Current Sense Tranformer", Manufacturer="Pulse Engineering", Supplier Part Number 1=553-1529-1-ND
U1: library part CMP-0071922-2, "Full-Bridge PWM Controller with Integrated MOSFET Drivers, 28-pin TSSOP-EP, 2500 Reel", Manufacturer="Texas Instruments", PackageTopMarking=NSUZXYTTE#*LM5045*MH, PowerWise=Y
U3: library part CMP-0006166-3, "Optocoupler, 3.75 kV, 80-160% CTR, SMT", Manufacturer=Vishay-Semiconductor, Supplier Part Number 1=TCMT1107CT-ND, Voltage_Isolation_Vrms=3.75kV
U4: library part CMP-0084708-1, "RRIO, High Output Current & Unlimited Cap Load Op Amp, DBV0005A (SOT-23-5)", Alternate Manufacturer="Texas Instruments", Operating Temperature Range="-40 to 85 C", Rating=Catalog
U5: library part CMP-0033063-1, "Precision Micropower Shunt Voltage Reference, 0.2% accuracy, 1.2 V, 15 ppm / degC, 12 mA, -40 to 85 degC, 3-pin SOT-23 (DBZ), Green (RoHS & no Sb/Br)", Manufacturer="Texas Instruments", Rating=Catalog, Temp Coeff(Max)(ppm/ degree C)=100, Temp Coeff(Typ)(ppm/ degree C)=15

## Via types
v1: diameter 0.7, hole 0.3, Top Layer to Bottom Layer, 68 vias
v2: diameter 0.9, hole 0.5, Top Layer to Bottom Layer, tented both sides, 30 vias
v3: diameter 0.7, hole 0.3, Top Layer to Bottom Layer, tented top, 25 vias
v4: diameter 0.9, hole 0.5, Top Layer to Bottom Layer, 22 vias
v5: diameter 0.9, hole 0.5, Top Layer to Bottom Layer, tented top, 20 vias
v6: diameter 0.7, hole 0.3, Top Layer to Bottom Layer, tented both sides, 18 vias
v7: diameter 0.6, hole 0.3, Top Layer to Bottom Layer, tented both sides, 18 vias
v8: diameter 0.7, hole 0.3, Top Layer to Bottom Layer, tented bottom, 5 vias
v9: diameter 0.6, hole 0.3, Top Layer to Bottom Layer, 3 vias
v10: diameter 0.9, hole 0.5, Top Layer to Bottom Layer, tented bottom, 2 vias
v11: diameter 0.8, hole 0.4, Top Layer to Bottom Layer, tented both sides, 1 vias

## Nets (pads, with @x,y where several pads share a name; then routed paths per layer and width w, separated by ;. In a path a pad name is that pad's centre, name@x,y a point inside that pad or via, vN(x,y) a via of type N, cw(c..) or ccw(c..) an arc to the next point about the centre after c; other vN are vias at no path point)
GND: C1.2 C2.2 C3.2 C4.2 C5.2 C6.2 C9.2 C10.2 C11.2 C13.1 C14.2 C22.2 C24.2 C25.2 C26.2 C27.2 C30.2 C34.2 D9.3 D11.2 P3.1 Q8.1 Q8.2 Q8.3 Q9.1 Q9.2 Q9.3 Q12.3 Q13.3 R9.1 R14.1 R15.1 R16.1 R18.1 R34.1 R35.1 U1.9 U1.15 U1.22 U1.29@23.284,32.909 | length 23.2
  Top Layer w0.4: Q12.3@8.631,24.969 10.152,24.969 R34.1@10.452,25.269 ; C10.2@14.3,4.445 14.3,3.353 v4(14.351,3.302) ; Q13.3@15.432,25.568 16.343,25.568 v6(16.393,25.618) 16.736,25.961 R35.1@17.409,25.961
  Top Layer w0.7: R34.1@10.452,25.269 10.49,25.307 v6(10.49,25.744) ; v6(12.446,8.509) v8(12.458,5.69)
  Bottom Layer w0.4: C11.2@22.949,27.051 22.949,29.948 U1.22@22.959,29.959 22.959,32.584 v9(23.284,32.909) ; U1.29@24.257,34.163 U1.9@24.259,35.859 24.259,37.775 25.057,38.573 R14.1@25.057,39.37 C26.2@25.057,41.021 ; U1.15@27.509,29.959 v6(28.996,29.959)
  other v1: 13.716,14.604 17.018,14.605 15.367,15.494 19.685,15.493 23.495,15.494 28.448,15.494
  other v3: 24.257,15.494 29.337,15.494
  other v5: 31.465,29.113 31.465,30.51
  other v7: 23.284,31.609 24.584,31.609 25.984,31.609 27.284,31.609 19.279,31.75 20.574,31.75 21.996,31.75 19.284,32.909 20.584,32.909 25.984,32.909 27.284,32.909 19.284,34.209 20.584,34.209 21.984,34.209 23.284,34.209 24.584,34.209 25.984,34.209 27.284,34.209
  other v8: 12.446,7.112
  other v9: 21.984,32.909 24.584,32.909
IGND: C7.2 C8.2 C13.2 C17.2 C18.2 C19.2 C20.2 C21.2 C23.2 C33.2 C36.2 C37.1 C38.2 C39.2 D6.2 D18.1 D18.2 D19.1 D19.2 P7.1 P8.1 R11.1 R29.2 U4.2 U5.2 | length 27
  Top Layer w0.5: v10(65.024,40.132) 65.222,40.33 C37.1@66.946,40.33 67.023,40.254 67.023,38.065 66.523,37.565 ; U4.2@65.648,37.565 66.523,37.565 ; C38.2@67.022,34.671 67.023,37.065 66.523,37.565
  Top Layer w0.6: P8.1@57.277,34.417 57.277,32.575 58.394,31.458 R29.2@61.606,31.458
  Bottom Layer w0.5: v4(42.439,32.757) 42.439,35.309 43.216,36.086 ; C33.2@55.029,38.608 55.104,38.683 v1(55.104,39.712) ; C7.2@58.995,27.094 v4@59.561,27.094
  Bottom Layer w0.6: v4(59.817,27.051) 60.756,27.99 60.756,28.678 60.767,28.689 60.767,29.477 60.756,29.488 D6.2@60.756,31.496
  Bottom Layer w0.8: C7.2@58.674,27.051 v4(59.817,27.051) ; C7.2@58.952,27.051 C7.2@58.995,27.094
  other v2: 61.849,20.371 68.377,20.371 70.18,20.396 72.136,20.447
  other v5: 73.406,5.588 77.216,5.588 77.216,7.62 73.406,7.684 73.406,9.652 77.216,9.652 77.216,28.448 38.323,29.183 73.406,29.464 77.216,30.48 38.323,30.51 73.406,30.988 73.406,32.512 77.216,32.512
LO2: Q9.4 Q12.2 Q12.5 R34.2 U1.20 | length 50.6
  Top Layer w0.4: v5(7.366,28.702) 7.681,28.387 Q12.5@7.681,27.419 7.681,26.454 7.941,26.194 ; Q12.2@7.681,24.969 7.681,25.934 7.941,26.194 ; R34.2@10.452,26.869 9.856,26.869 9.181,26.194 7.941,26.194
  Layer 3 w0.6: 18.134,30.822 22.137,30.822 22.187,30.772 22.279,30.772 24.588,28.463 24.588,28.371 v6(24.638,28.321)
  Layer 3 w0.7: v4(11.643,10.528) 9.347,12.824 9.347,22.05 7.366,24.031 v5(7.366,28.702) 7.366,29.497 8.628,30.759 9.573,30.759 9.636,30.822 18.134,30.822
  Bottom Layer w0.4: U1.20@24.259,29.959 24.259,28.7 v6(24.638,28.321)
  Bottom Layer w0.5: v4(11.643,10.528) 12.466,9.705 Q9.4@13.587,9.705
NetC1_1: C1.1 C2.1 C3.1 C4.1 C6.1 C27.1 P1.1 Q6.5 Q6.6 Q6.7 Q6.8 Q6.9@26.543,19.685 Q7.5 Q7.6 Q7.7 Q7.8 Q7.9@26.531,7.8 R6.2 R8.2 | length 11.1
  Bottom Layer w0.5: P1.1@7.493,34.29 7.8,34.29 9.182,32.908 ; R6.2@9.256,37.563 9.256,32.982 9.182,32.908 ; R8.2@12.963,31.934 10.156,31.934 9.182,32.908
  other v1: 13.716,11.304 17.018,11.303 19.05,12.192 15.367,12.319
  other v3: 25.019,6.522 26.543,6.522 28.067,6.522 25.019,7.792 26.543,7.792 28.067,7.792 25.019,9.062 26.543,9.062 28.067,9.062 20.32,12.192 23.241,12.192 24.511,12.192 28.448,12.192 29.337,12.192 25.019,18.415 26.543,18.415 28.067,18.415 25.019,19.685 26.543,19.685 28.067,19.685 25.019,20.955 26.543,20.955 28.067,20.955
NetC9_1: C9.1 D7.3 Q3.2 Q3.4 R4.2 | length 9.8
  Top Layer w0.8: v4(5.893,9.449) 6.604,10.16 R4.2@8.001,10.16 8.001,9.65 9.017,8.634 Q3.2@9.017,7.415
  Bottom Layer w0.5: v4(5.893,9.449) 6.354,9.91 C9.1@7.291,9.91 7.291,9.453 8.307,8.437 D7.3@8.307,7.712
  other v1: 8.382,3.302 9.271,3.302 8.454,4.231 10.517,4.993 10.517,5.867
NetC10_1: C10.1 D2.2 Q3.3 | length 46.6
  Top Layer w0.5: v4(6.325,7.599) 6.341,7.615 Q3.3@7.517,7.615 ; v5(12.192,3.556) 12.192,3.937 C10.1@12.7,4.445 ; v4(21.552,26.51) 22.949,27.907 22.949,29.227 D2.2@21.849,30.327
  Layer 3 w0.5: v4(6.325,7.599) v4@6.534,7.599 ; v5(12.192,3.556) 11.455,3.556 10.869,4.142 9.991,4.142 v4@6.534,7.599 ; v4(21.552,26.51) 19.236,24.194 13.364,24.194 11.091,21.921 11.091,12.646 12.583,11.154 12.583,10.043 10.139,7.599 v4@6.534,7.599
NetC12_1: C12.1 Q7.1 Q7.2 Q7.3 Q9.5 Q9.6 Q9.7 Q9.8 Q9.9@17.387,7.8 T1.5 U1.16 | length 33.8
  Layer 3 w0.6: v4(16.293,9.726) 21.095,9.726 21.725,9.097 23.638,9.097 25.9,11.358 25.9,14.577 27.686,16.363 28.968,16.363 29.967,17.362 29.967,26.726 v4(29.642,27.051)
  Bottom Layer w0.4: U1.16@26.859,29.959 26.859,29.148 26.884,29.123 28.486,27.521 C12.1@28.486,27.051
  Bottom Layer w0.5: C12.1@28.486,27.051 v4(29.642,27.051)
  other v1: 22.733,6.502
  other v2: 22.758,5.131
  other v6: 22.309,7.8
NetC12_2: C12.2 D8.1 U1.18 | length 3.7
  Bottom Layer w0.4: U1.18@25.559,29.959 25.559,27.996 26.504,27.051 C12.2@26.886,27.051
NetC14_1: C14.1 R8.1 U1.28 | length 4.9
  Bottom Layer w0.4: C14.1@17.018,31.609 18.668,29.959 U1.28@19.059,29.959
  Bottom Layer w0.5: R8.1@14.995,31.934 15.32,31.609 C14.1@17.018,31.609
NetC15_1: C15.1 Q6.1 Q6.2 Q6.3 Q8.5 Q8.6 Q8.7 Q8.8 Q8.9@17.457,19.748 T2.4 T2.5 T2.7 U1.27 | length 11.2
  Bottom Layer w0.4: C15.1@18.116,27.096 18.116,27.429 19.443,28.756 19.443,28.759 19.709,29.025 U1.27@19.709,29.959
  Bottom Layer w0.8: Q8.9@17.457,19.748 17.366,19.839 17.366,26.346 C15.1@18.116,27.096
  other v1: 22.733,19.685
  other v2: 22.089,16.815
  other v6: 22.479,18.415
NetC15_2: C15.2 D12.1 U1.25 | length 3.8
  Bottom Layer w0.4: C15.2@19.716,27.096 20.466,27.096 21.009,27.64 U1.25@21.009,29.959
NetC16_1: C16.1 D1.2 D4.3 D15.3 L4.2
  other v1: 44.244,13.726 45.397,13.708 46.53,13.726 44.244,14.996 45.397,14.978 46.53,14.996 44.244,16.266 45.397,16.248 46.53,16.266 44.244,17.536 45.387,17.536 46.53,17.536 37.678,19.859 36.525,19.877 38.811,19.877 37.678,21.129 36.525,21.147 38.811,21.147 37.678,22.399 36.525,22.417 38.811,22.417 36.525,23.687 37.668,23.687 38.811,23.687
NetC16_2: C16.2 R11.2
NetC22_1: C22.1 U1.13 | length 5.8
  Bottom Layer w0.4: U1.13@26.859,35.859 26.859,36.759 27.185,37.084 27.767,37.084 28.764,36.086 28.764,35.648 29.36,35.052 C22.1@30.531,35.052
NetC23_1: C23.1 D1.1 R17.1
NetC24_1: C24.1 U1.14 | length 4
  Bottom Layer w0.4: U1.14@27.509,35.859 29.967,33.401 C24.1@30.531,33.401
NetC25_1: C25.1 U1.12 | length 6.2
  Bottom Layer w0.4: U1.12@26.234,35.884 U1.12@26.209,35.859 26.209,36.957 26.936,37.684 28.015,37.684 28.996,36.703 C25.1@30.531,36.703
NetC29_1: C29.1 R22.1 R28.2 R29.1 U4.4 | length 16.8
  Top Layer w0.5: R28.2@61.606,34.965 R29.1@61.606,33.058 63.072,33.058 R22.1@63.872,32.258 63.872,32.757 64.643,33.528 67.872,33.528 68.398,34.054 U4.4@68.398,36.615 69.77,36.615 70.506,37.351 C29.1@70.506,39.078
